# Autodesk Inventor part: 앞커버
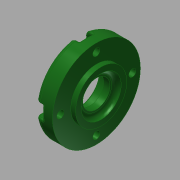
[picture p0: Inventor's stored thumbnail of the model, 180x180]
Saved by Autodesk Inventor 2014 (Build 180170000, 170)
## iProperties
Created: 2015-11
Part Number: 앞커버
Material: 알루미늄 6061
Document SubType Name: Modeling
Designer: mduedu
Density: 1 g/cm^3
Appearance: Smooth - Dark Forest Green
Author: mduedu
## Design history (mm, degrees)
sketch "스케치1"
  geometry: L1 (-7, 0)-(7, 0); L2 (-7, 0)-(-7, 27.5); L3 (-7, 27.5)-(4, 27.5); L4 (4, 27.5)-(4, 16); L5 (4, 16)-(7, 16); L6 (7, 16)-(7, 0); 2 further points
  constraints: 12 end point, 3 perpendicular, 2 parallel, 1 coincident, 1 horizontal, 1 midpoint
  dimensions: "d0" = 14 distance of L1.start L1.end; "d1" = 55 diameter of L3 L1; "d2" = 3 distance of L4.end L5.end; "d3" = 32 diameter of L5 L1
revolve "회전1" sketch "스케치1" stored, may be unused: angle "d4" = 90 deg
hole "구멍1" diameter "d7" = 25; stored, may be unused: countersink angle "d11" = 90 deg, drill point angle "d13" = 0 deg; dims "d5" = 10, "d6" = 10, "d8" = 6, "d9" = 4, "d10" = 2, "d12" = 3
hole "구멍2" diameter "d16" = 25; stored, may be unused: countersink angle "d20" = 90 deg, drill point angle "d22" = 0 deg; dims "d17" = 6, "d18" = 4, "d19" = 2, "d21" = 7, "d63" = 10, "d64" = 10
hole "구멍3" diameter "d25" = 17; stored, may be unused: countersink angle "d29" = 90 deg, drill point angle "d31" = 0 deg; dims "d23" = 10, "d24" = 10, "d26" = 6, "d27" = 4, "d28" = 2, "d30" = 4.2
chamfer "모따기1" distance "d32" = 0.6; stored, may be unused: second distance "d33" = 2, angle "d34" = 30 deg
fillet "모깎기1" dims "d35" = 0.3
fillet "모깎기2" dims "d36" = 3
fillet "모깎기3" dims "d37" = 3
sketch "스케치2" dims "d39" = 45
  geometry: C1 r 12.846 at (0, 0) reference; C2 r 24.5 at (0, 0) reference; 6 further points
  constraints: 2 vertical alignment, 1 coincident, 7 other
  dimensions: "d42" = 360 deg dimension on point (0, 0) point (0, 22.5) (derived)
sketch "스케치3"
  geometry: 8 further points
  constraints: 4 coincident
hole "구멍4" sketch "스케치3" at (-22.5, 0), (0, -22.5), (22.5, 0), (0, 22.5) diameter "d44" = 4.5; stored, may be unused: countersink angle "d48" = 90 deg, drill point angle "d50" = 0 deg; dims "d45" = 6, "d46" = 8, "d47" = 4.6, "d49" = 8
sketch "스케치4"
  geometry: L1 (-4, 0)-(-4, -4.708); L2 (4, 0)-(4, -4.708); A1 r 4 centre (0, 0) between (-4, 0) and (4, 0) reference; A2 r 27.5 centre (0, 22.5) between (-4, -4.708) and (4, -4.708) reference; 3 further points
  constraints: 4 end point, 4 point on circle, 2 tangent, 1 parallel, 1 vertical
extrude "돌출1" cut sketch "스케치4" stored distance "d51" = 0; taper "d52" = 0 deg
fillet "모깎기5" dims "d56" = 0.3
fillet "모깎기6" dims "d57" = 1
node "솔리드1"
pattern_circular "원형 패턴1" dims angle "d54" = 360 deg
